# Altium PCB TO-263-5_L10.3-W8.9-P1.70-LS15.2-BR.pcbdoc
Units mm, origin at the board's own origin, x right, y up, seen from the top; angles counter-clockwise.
Board outline 29.39 x 23.13 mm, 2 copper layers (Top Layer, Bottom Layer), stack 0 mm thick; 1 components, 0 nets, 6 pads, 0 vias.
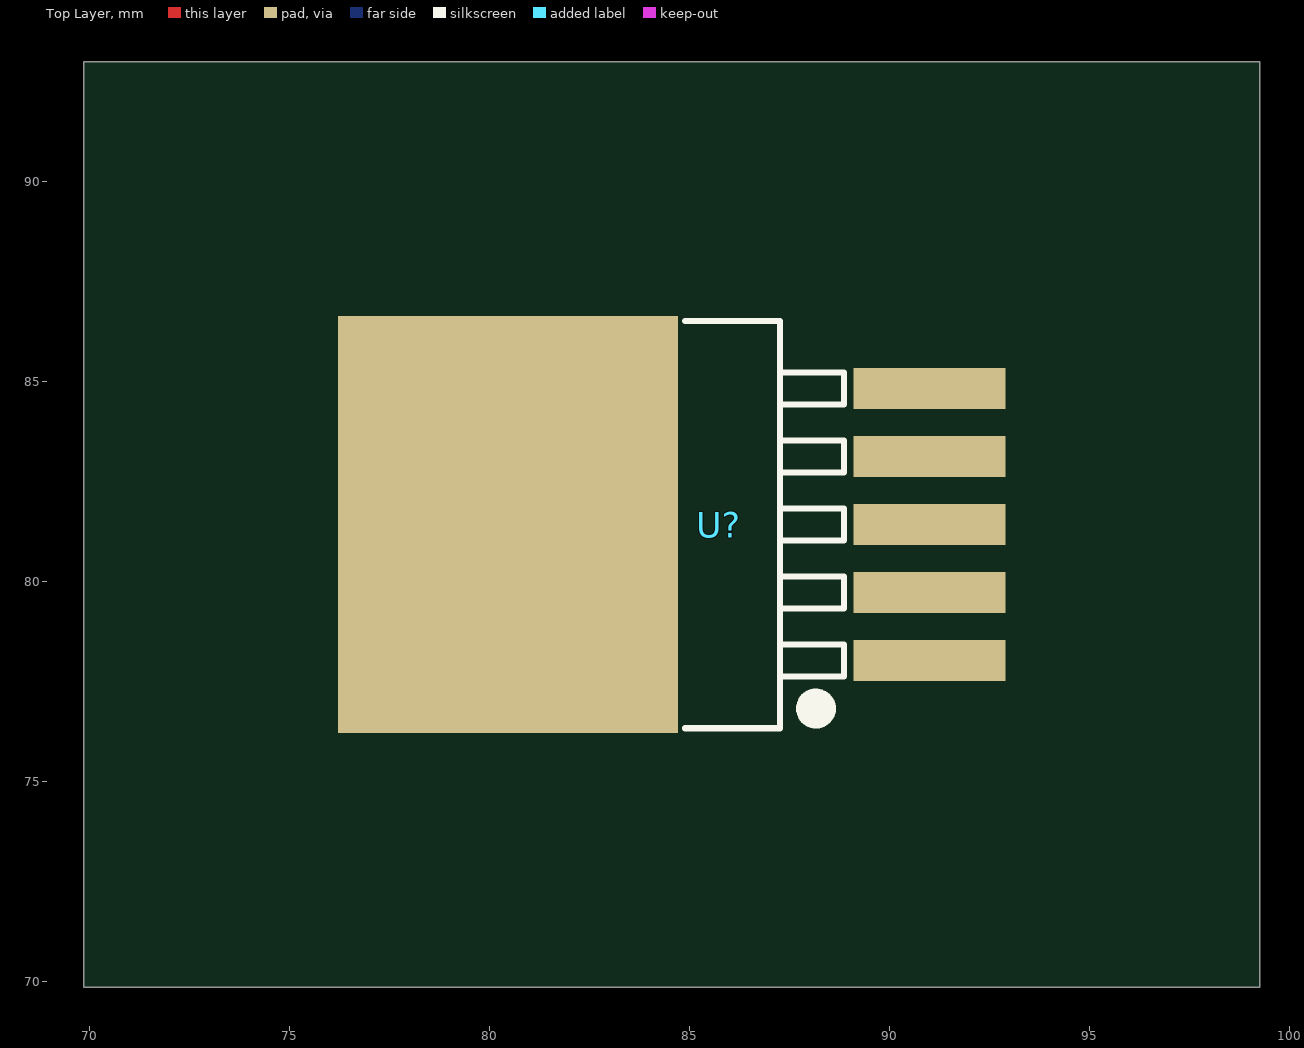
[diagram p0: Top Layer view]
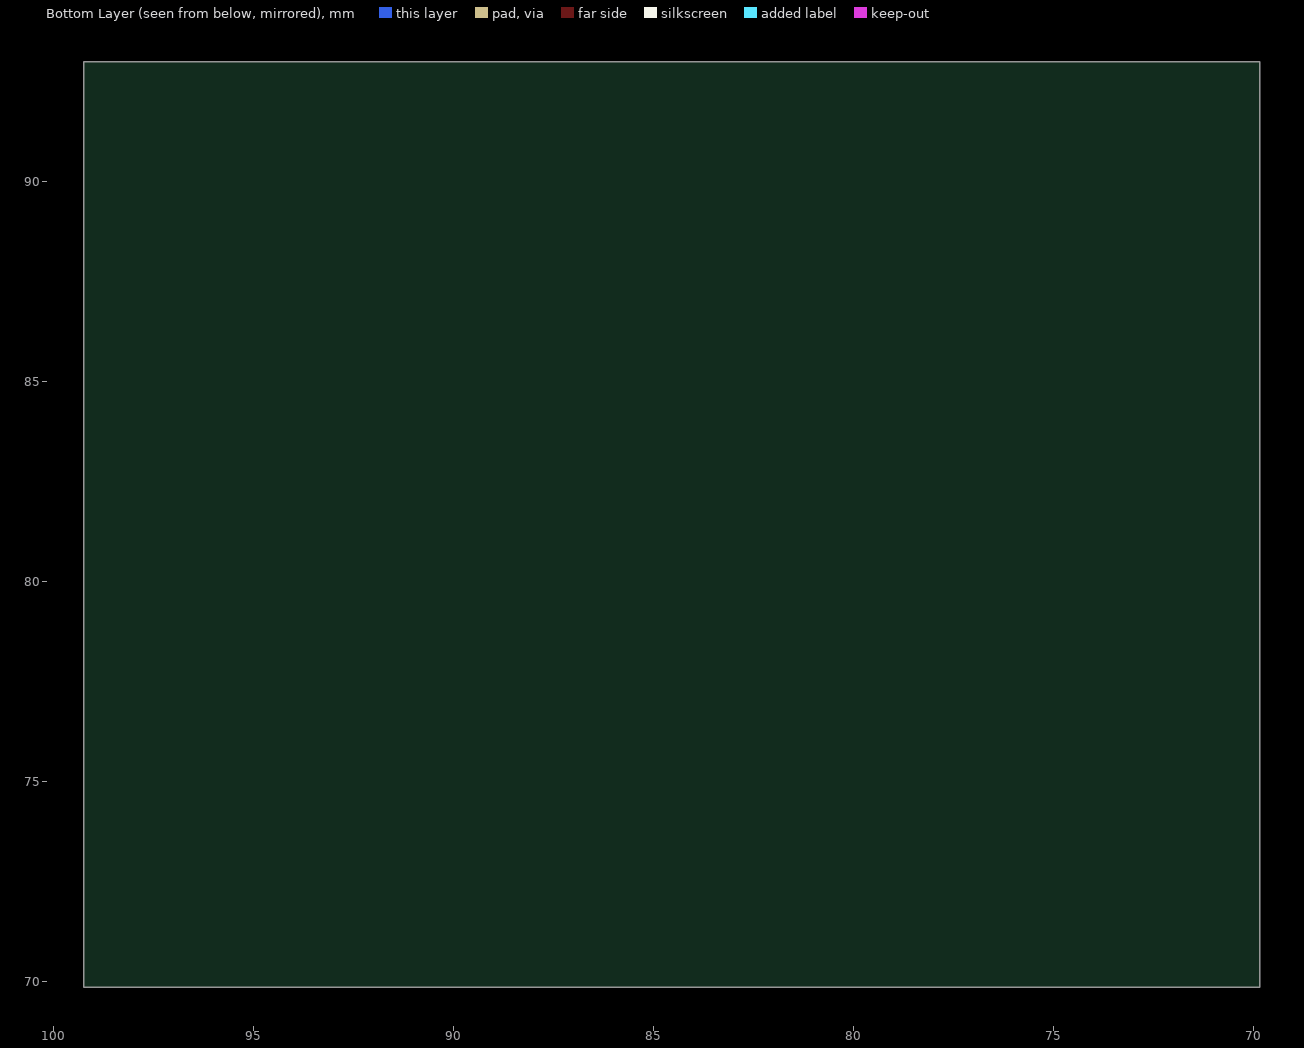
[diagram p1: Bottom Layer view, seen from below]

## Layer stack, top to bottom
Top Layer: signal copper (thickness not stored)
Bottom Layer: signal copper (thickness not stored)

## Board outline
99.242,69.85 69.85,69.85 69.85,92.981 99.242,92.981

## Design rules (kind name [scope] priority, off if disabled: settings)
PasteMaskExpansion "Paste Mask Expansion" [All] p1: expansion=0
SolderMaskExpansion "Solder Mask Expansion" [IsVia] p1: expansion=-25.4 istentingtop=TRUE
SolderMaskExpansion "Solder Mask Expansion" [All] p2: expansion=0.051 istentingtop=FALSE

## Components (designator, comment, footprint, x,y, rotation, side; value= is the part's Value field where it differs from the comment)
U? "" TO-263-5_L10.3-W8.9-P1.70-LS15.2-BR 85.721,81.416 r0 top

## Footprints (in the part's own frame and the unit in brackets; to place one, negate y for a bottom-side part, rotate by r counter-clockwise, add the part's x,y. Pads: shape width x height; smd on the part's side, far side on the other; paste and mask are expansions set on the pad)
TO-263-5_L10.3-W8.9-P1.70-LS15.2-BR [mm]
  rect 3.8x1.02 smd: 1(5.271,-3.4) 2(5.271,-1.7) 3(5.271,0) 4(5.271,1.7) 5(5.271,3.4)
  rect 8.5x10.431 smd: 6(-5.271,0)
  silkscreen extent -0.84,-5.09 3.13,5.09

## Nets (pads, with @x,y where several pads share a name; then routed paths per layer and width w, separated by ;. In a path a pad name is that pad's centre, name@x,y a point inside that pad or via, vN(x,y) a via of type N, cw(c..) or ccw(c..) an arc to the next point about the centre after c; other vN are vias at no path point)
pads on no net: U?.1 U?.2 U?.3 U?.4 U?.5 U?.6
